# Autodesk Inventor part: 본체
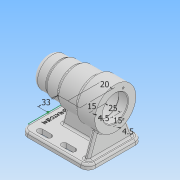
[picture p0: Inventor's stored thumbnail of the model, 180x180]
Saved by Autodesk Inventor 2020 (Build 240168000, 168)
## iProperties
Created: 2021-10
Part Number: 본체
Material: 일반
Document SubType Name: Modeling
Designer: user
Density: 1 g/cm^3
Appearance: 기본값
Author: user
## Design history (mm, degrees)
sketch "스케치1"
  geometry: L1 (0, 0)-(0, 25); L2 (0, 25)-(24, 25); L3 (112, 21)-(97, 21); L4 (97, 21)-(97, 21); L5 (94, 24)-(46, 24); L6 (43, 21)-(43, 21); L7 (43, 21)-(31.3, 21); L8 (31, 20.7)-(31, 17.5); L9 (31, 17.5)-(13.3, 17.5); L10 (13, 17.2)-(13, 16); L11 (13, 16)-(9.3, 16); L12 (9, 15.7)-(9, 10.5); L13 (9, 10.5)-(9, 10.5); L14 (6, 7.5)-(6, 0); L15 (6, 0)-(0, 0); L16 (24, 25)-(24, 27); L17 (24, 27)-(46, 27); L18 (46, 27)-(46, 30); L19 (80, 34)-(112, 34); L20 (112, 34)-(112, 21); L21 (46, 30)-(80, 30); L22 (80, 30)-(80, 34); A1 r 0.3 centre (9.3, 15.7) between (9.3, 16) and (9, 15.7); A2 r 0.3 centre (13.3, 17.2) between (13.3, 17.5) and (13, 17.2); A3 r 0.3 centre (31.3, 20.7) between (31.3, 21) and (31, 20.7); A4 r 3 centre (9, 7.5) between (9, 10.5) and (6, 7.5); A5 r 3 centre (46, 21) between (46, 24) and (43, 21); A6 r 3 centre (94, 21) between (97, 21) and (94, 24); 9 further points
  constraints: 44 end point, 14 perpendicular, 14 point on line, 12 point on circle, 12 tangent, 6 centre point, 4 equal radius, 3 vertical, 2 horizontal, 1 parallel
  dimensions: "d0" = 25 distance of L1.start L1.end; "d1" = 24 distance of L1.end L2.end; "d3" = 46 horizontal distance of L18.end L1.end; "d4" = 80 horizontal distance of L19.start L1.end; "d5" = 112 horizontal distance of L19.end L1.end; "d6" = 2 distance of L2.end L16.end; "d7" = 3 distance of L17.end L18.end; "d8" = 4 distance of L21.end L19.start; "d9" = 13 distance of L19.end L3.start; "d10" = 15 distance of L3.start L3.end; "d11" = 3 distance of L3.end point (97, 24); "d12" = 54 distance of point (97, 24) point (43, 24); "d13" = 24 distance from line of L14.end L5; "d14" = 10.5 distance of point (6, 10.5) L14.end; "d16" = 18 distance of L8.end point (13, 17.5); "d17" = 12 distance of L6.end point (31, 21); "d18" = 3 distance from line of L12.end L14; "d19" = 4 horizontal distance of L10.end L12.end; "d20" = 17.5 distance from line of L14.end L9; "d23" = 0.3 radius of A1; "d24" = 3 radius of A4; "d80" = 16 distance from line of L14.end L11
revolve "회전1" sketch "스케치1" stored, may be unused: angle "d22" = 90 deg
chamfer "모따기1" distance "d25" = 1; stored, may be unused: second distance "d26" = 2, angle "d27" = 45 deg
node "작업 평면1"
sketch "스케치2"
  geometry: L1 (0, -45)-(-112, -45); L2 (-112, -45)-(-112, 45); L3 (-112, 45)-(0, 45); L4 (0, 45)-(0, -45); L5 (-112, 34)-(-112, -34) reference; L6 (0, 25)-(0, -25) reference; 2 further points
  constraints: 8 end point, 2 parallel, 1 coincident, 1 collinear, 1 horizontal, 1 midpoint, 1 perpendicular
  dimensions: "d29" = 112 distance of L2.end L3.end; "d30" = 90 distance of L1.end L2.end
extrude "돌출1" join sketch "스케치2" distance "d31" = 8; taper "d32" = 0 deg
sketch "스케치3"
  geometry: L1 (104, 37)-(96, 37); L2 (96, 37)-(96, -37); L3 (96, -37)-(104, -37); L4 (104, -37)-(104, 37); L5 (104, 4)-(27, 4); L6 (27, 4)-(27, -4); L7 (27, -4)-(104, -4); L8 (104, -4)-(104, 4); L9 (112, -45)-(112, 45) reference; 3 further points
  constraints: 16 end point, 4 parallel, 2 horizontal, 2 perpendicular, 1 horizontal alignment, 1 midpoint, 1 point on line
  dimensions: "d33" = 8 distance between parallel lines of L4 L2; "d34" = 8 distance between parallel lines of L7 L5; "d35" = 8 distance between parallel lines of L9 L4; "d36" = 77 distance of L5.start L5.end; "d37" = 8 horizontal distance of L9.end L1.start; "d38" = 8 horizontal distance of L9.start L3.end
extrude "돌출2" join sketch "스케치3" stored distance "d39" = 8; taper "d40" = 0 deg
sketch "스케치4"
  geometry: L1 (-41, -8)-(-41, 0) reference; L2 (-41, 0)-(0, 0) reference; L3 (0, 0)-(0, 28.236) reference; L4 (8, 28.236)-(8, 0) reference; L5 (8, 0)-(49, 0) reference; L6 (49, 0)-(49, -8) reference; L7 (49, -8)-(-41, -8) reference; L8 (0, 0)-(8, 0) reference; L9 (-19.409, 37.342)-(-33, 0); C1 r 21 at (4, 62) reference; A1 r 34 centre (4, 62) between (8, 28.236) and (0, 28.236) reference; A2 r 34 centre (4, 62) between (0, 28.236) and (8, 28.236) reference; 1 further point
  constraints: 2 end point, 1 point on circle, 1 point on line
  dimensions: "d41" = 110 deg angle of L2 L9; "d42" = 8 distance of L1.end L9.end
extrude "돌출3" join sketch "스케치4" distance "d43" = 8; taper "d44" = 0 deg
sketch "스케치5"
  geometry: 2 further points
  constraints: 1 horizontal alignment
  dimensions: "d45" = 26 distance of point (0, 0) point (-26, 0)
hole "구멍1" sketch "스케치5" at (-26, 0) diameter "d46" = 3.242; stored, may be unused: countersink angle "d50" = 90 deg, drill point angle "d52" = 118 deg; dims "d47" = 8, "d48" = 4, "d49" = 2, "d51" = 11
fillet "모깎기1" dims "d56" = 8
fillet "모깎기2" dims "d57" = 3
fillet "모깎기6" dims "d61" = 12
fillet "모깎기7" dims "d62" = 3
sketch "스케치6"
  geometry: L1 (15.5, 33)-(39.5, 33); L2 (20, 37.5)-(35, 37.5); L3 (35, 28.5)-(20, 28.5); L4 (55.5, 33)-(79.5, 33); L5 (60, 37.5)-(75, 37.5); L6 (75, 28.5)-(60, 28.5); L7 (0, 33)-(0, -33) reference; A1 r 4.5 centre (20, 33) between (20, 37.5) and (20, 28.5); A2 r 4.5 centre (35, 33) between (35, 28.5) and (35, 37.5); A3 r 4.5 centre (60, 33) between (60, 37.5) and (60, 28.5); A4 r 4.5 centre (75, 33) between (75, 28.5) and (75, 37.5); 3 further points
  constraints: 16 end point, 12 point on circle, 8 tangent, 4 centre point, 4 point on line, 3 parallel, 2 midpoint, 1 horizontal, 1 horizontal alignment
  dimensions: "d64" = 15 distance of A2.centre A1.centre; "d65" = 15 distance of A4.centre A3.centre; "d66" = 25 distance of A3.centre A2.centre; "d67" = 20 distance from line of L7 A1.centre; "d68" = 4.5 radius of A4; "d69" = 4.5 radius of A2; "d70" = 33 vertical distance of point (0, 0) A1.centre
extrude "돌출4" cut sketch "스케치6" distance "d71" = 53.5; taper "d72" = 0 deg
sketch "스케치7"
  geometry: 2 further points
  constraints: 1 horizontal alignment, 1 other
  dimensions: "d73" = 12 distance of point (0, 0) point (12, 0)
feature "엠보싱1" sketch "스케치7" dims "d0" = 25, "d1" = 24, "d3" = 46, "d4" = 80, "d5" = 112, "d6" = 2, "d7" = 3, "d8" = 4, "d9" = 13, "d10" = 15, "d11" = 3, "d12" = 54, "d13" = 24, "d14" = 10.5, "d16" = 18, "d17" = 12, "d18" = 3, "d19" = 4, "d20" = 17.5, "d23" = 0.3, "d24" = 3, "d74" = 0.5, "d75" = 0, "d80" = 16
feature "면 기울기1" dims angle "d76" = 15 deg
fillet "모깎기8" dims "d77" = 3
fillet "모깎기9" dims "d78" = 3
node "솔리드1"
mirror "미러1"
pattern_circular "원형 패턴1" dims angle "d54" = 360 deg
mirror "미러2"
node "작업 평면2"
node "작업 평면3"
node "절단 모서리 투영1"
feature "A9D066F2-1C7D-4E18-AEED-F7BC21143FA4" dims "d46" = 3.242, "d47" = 8, "d48" = 4, "d49" = 2, "d50" = 90 deg, "d51" = 11, "d52" = 118 deg
